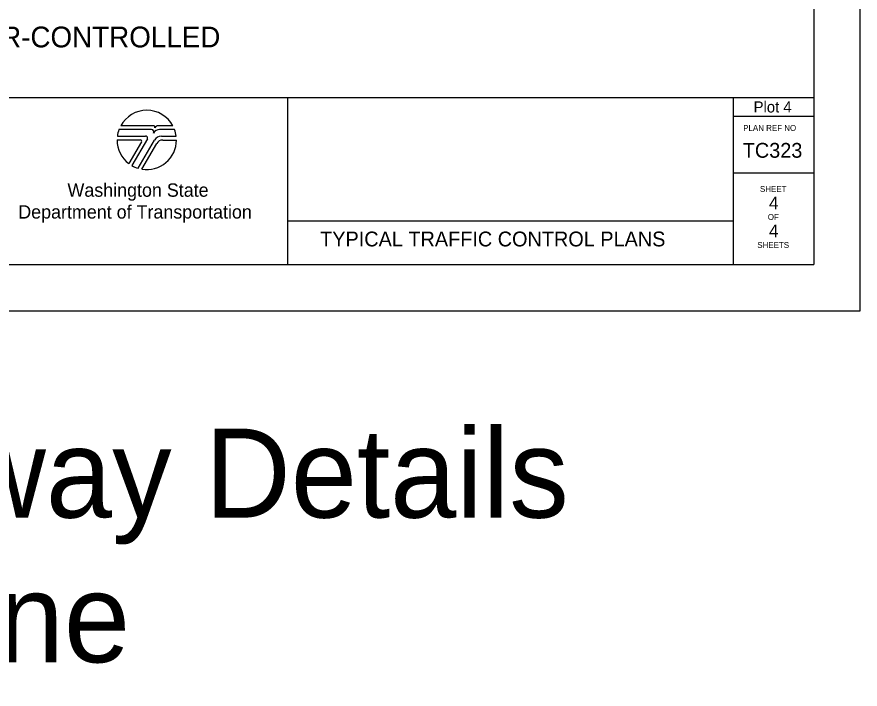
# Model space of a CAD drawing. Extents: x 99999.1 to 100095.7, y 99995 to 100010.7.
# Drawn here: x 100070.38 to 100076.06, y 99997.14 to 100001.67 of the extents above; entities that cross this region are included whole.
import ezdxf

# ---------------------------------------------------------------- set-up
doc = ezdxf.new("R2010")
doc.units = 0
for name, color, linetype in [('SH_DE_DetailHeading1Text', 7, 'Continuous'), ('SH_GI_PlotLimits', 7, 'Continuous'), ('SH_GI_SheetBorder', 7, 'Continuous'), ('SH_GI_SheetLocationText', 7, 'Continuous'), ('SH_GI_SheetTextInCells', 7, 'Continuous'), ('SH_GI_TitleBlockText', 7, 'Continuous'), ('SH_GI_WSDOTLogo', 7, 'Continuous')]:
    doc.layers.add(name, color=color, linetype=linetype)

msp = doc.modelspace()

# ---------------------------------------------------------------- linework, layer by layer
at = {"layer": 'SH_GI_PlotLimits'}
msp.add_lwpolyline([(100059.0625, 99999.6875), (100076.0625, 99999.6875), (100076.0625, 100010.6875), (100059.0625, 100010.6875)], close=True, dxfattribs=at)
at = {"layer": 'SH_GI_SheetBorder'}
for p, q in [((100075.75, 100010.375), (100075.75, 100000)), ((100060, 100001.1259), (100075.75, 100001.1259)), ((100072.2055, 100001.1259), (100072.2055, 100000)), ((100075.2079, 100001.1259), (100075.2079, 100000)), ((100075.2079, 100001.0008), (100075.75, 100001.0008)), ((100075.2079, 100000.6176), (100075.75, 100000.6176)), ((100072.2055, 100000.2955), (100075.2079, 100000.2955)), ((100060, 100000), (100075.75, 100000))]:
    msp.add_line(p, q, dxfattribs=at)
at = {"layer": 'SH_GI_WSDOTLogo'}
for p, q in [((100071.2894, 100000.9094), (100071.0697, 100000.9094)), ((100071.303, 100000.9354), (100071.0815, 100000.9354)), ((100071.433, 100000.9354), (100071.3351, 100000.9354)), ((100071.343, 100000.9094), (100071.3429, 100000.9094)), ((100071.4448, 100000.9094), (100071.343, 100000.9094)), ((100071.0572, 100000.84), (100071.2148, 100000.84)), ((100071.059, 100000.8661), (100071.2496, 100000.8661)), ((100071.222, 100000.8277), (100071.1364, 100000.6807)), ((100071.261, 100000.8464), (100071.1567, 100000.6672)), ((100071.1989, 100000.6487), (100071.3089, 100000.839)), ((100071.3558, 100000.8661), (100071.4555, 100000.8661)), ((100071.3655, 100000.8394), (100071.4572, 100000.8394)), ((100071.2244, 100000.6428), (100071.3242, 100000.8156))]:
    msp.add_line(p, q, dxfattribs=at)
for centre, radius, start, end in [((100071.2572, 100000.84), 0.2, 28.4787, 151.532), ((100071.2572, 100000.84), 0.2, 159.696, 172.5057), ((100071.2894, 100000.8946), 0.0148, 327.8418, 89.9985), ((100071.3429, 100000.861), 0.0484, 89.9953, 147.8238), ((100071.303, 100000.9263), 0.00903, 329.8742, 90.0033), ((100071.3352, 100000.9066), 0.0287, 90.0072, 148.1676), ((100071.2572, 100000.84), 0.2, 7.4943, 20.2941), ((100071.2572, 100000.84), 0.2, 179.9986, 232.8433), ((100071.2149, 100000.8318), 0.0082, 329.7436, 90), ((100071.2572, 100000.84), 0.2, 260.5455, 359.8086), ((100071.2497, 100000.853), 0.0131, 329.7683, 90), ((100071.3558, 100000.8119), 0.0542, 90, 149.9974), ((100071.3654, 100000.7918), 0.0476, 90, 150.0543), ((100071.2572, 100000.84), 0.2, 239.7929, 253.0448)]:
    msp.add_arc(centre, radius, start, end, dxfattribs=at)

# ---------------------------------------------------------------- texts
at = {"layer": 'SH_DE_DetailHeading1Text'}
msp.add_text('PILOT CAR OPERATION FOR ALTERNATING 1-LANE, 2-WAY TRAFFIC: FLAGGER-CONTROLLED', height=0.14, rotation=360, dxfattribs=at).set_placement((100063.2129, 100001.4639))
at = {"layer": 'SH_GI_SheetBorder'}
msp.add_text('PLAN REF NO', height=0.040032, dxfattribs=at).set_placement((100075.2747, 100000.9008))
at = {"layer": 'SH_GI_SheetLocationText'}
for s, height, p in [('Plot 4', 0.075, (100075.3447, 100001.025)), ('Access & Intersecting Roadway Details', 0.6, (100060.1422, 99998.2946)), ('Separated Bike Lane', 0.6, (100063.6511, 99997.3196))]:
    msp.add_text(s, height=height, dxfattribs=at).set_placement(p)
at = {"layer": 'SH_GI_SheetTextInCells'}
for s, height, p in [('Washington State', 0.090072, (100070.7229, 100000.4571)), ('SHEET', 0.04003, (100075.3877, 100000.4896)), ('Department of Transportation', 0.090072, (100070.3916, 100000.3101)), ('OF', 0.04003, (100075.4406, 100000.3008)), ('SHEETS', 0.04003, (100075.3698, 100000.112))]:
    msp.add_text(s, height=height, dxfattribs=at).set_placement(p)
at = {"layer": 'SH_GI_TitleBlockText'}
for s, height, p in [('TC323', 0.1, (100075.2718, 100000.72)), ('4', 0.085, (100075.4485, 100000.3723)), ('4', 0.085, (100075.4485, 100000.1843)), ('TYPICAL TRAFFIC CONTROL PLANS', 0.1, (100072.4251, 100000.1224))]:
    msp.add_text(s, height=height, dxfattribs=at).set_placement(p)

doc.saveas('drawing.dxf')
